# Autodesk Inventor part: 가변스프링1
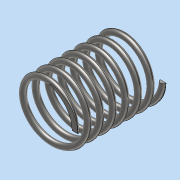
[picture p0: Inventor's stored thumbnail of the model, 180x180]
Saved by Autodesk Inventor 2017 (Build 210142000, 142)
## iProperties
Part Number: 가변스프링1
Material: 스테인레스 스틸
Document SubType Name: Modeling
Designer: MRC
Density: 8 g/cm^3
Appearance: 반연마
Mass: 10.8942 g
Surface Area: 27.565 cm^2
Volume: 1.36177 cm^3
Author: MRC
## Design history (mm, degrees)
sketch "스케치1"
  geometry: L1 (0, 0)-(10, 0); L2 (10, 0)-(10, 30.358); L3 (10, 30.358)-(0, 30.358); L4 (0, 30.358)-(0, 0); C1 r 1 at (10, 0)
  constraints: 8 end point, 2 parallel, 1 centre point, 1 coincident, 1 horizontal, 1 perpendicular
  dimensions: "d0" = 30.35829 distance of L3.end L1.start (derived); "d1" = 20 diameter of L2 L4; "d2" = 2 diameter of C1
feature "코일1" sketch "스케치1" pitch "d3" = 10; turns "d5" = 7; dims "d4" = 30.35829 (= d0), "d6" = 0, angle "d7" = 90 deg, angle "d8" = 90 deg, "d9" = 0, "d10" = 0
sketch "스케치2"
  geometry: L1 (-25, 30.358)-(25, 30.358); L2 (25, 30.358)-(25, 0); L3 (25, 0)-(-25, 0); L4 (-25, 0)-(-25, 30.358); L5 (0, 30.358)-(0, 0) reference; 2 further points
  constraints: 8 end point, 2 midpoint, 2 parallel, 1 coincident, 1 horizontal, 1 perpendicular
  dimensions: "d11" = 50 distance of L1.start L1.end
extrude "돌출1" sketch "스케치2" stored distance "d12" = 0; taper "d13" = 0 deg
node "솔리드1"
